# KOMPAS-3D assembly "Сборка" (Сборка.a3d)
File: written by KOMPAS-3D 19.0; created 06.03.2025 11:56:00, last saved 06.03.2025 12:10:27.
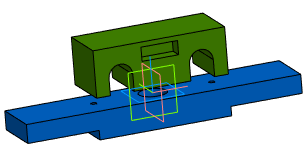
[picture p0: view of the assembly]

Document properties: Автор: user-2; Полное имя файла: D:\ОПР Врацкий\_Работы 2025\3D\Сборка.a3d

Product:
- Part/product: Сборка
    Масса: 6.00335
  - Component [detail]: Деталь  | Масса: 2.56307; source file: Скользун.m3d
  - Component [detail]: Деталь  | Масса: 3.44027; source file: Основание.m3d

Referenced files in D:\ОПР Врацкий\_Работы 2025\3D\: Основание.m3d, Скользун.m3d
